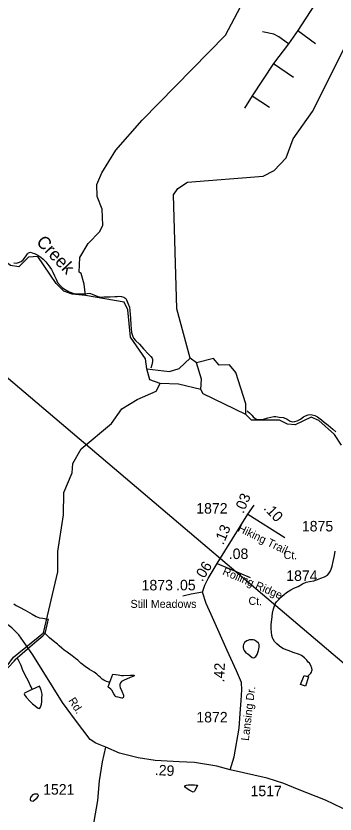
# Model space of a CAD drawing. Extents: x 2082433 to 2279600, y 546599 to 755198.
# Drawn here: x 2129173 to 2132963, y 651046 to 660530 of the extents above; entities that cross this region are included whole.
import ezdxf

# ---------------------------------------------------------------- set-up
doc = ezdxf.new("R2010")
doc.units = 0
for name, color, linetype in [('Exist Boundary Political Fire Districts', 7, 'Continuous'), ('Exist Hydrographic Creek Single Shore', 7, 'Continuous'), ('Exist Hydrographic Creek Single Shore Label', 7, 'Continuous'), ('Exist Hydrographic Misc Water Feature', 7, 'Continuous'), ('Exist Road Non-System Type 51', 7, 'Continuous'), ('Exist Road Secondary Mileage Hundredths English Label', 7, 'Continuous'), ('Exist Road Secondary Type 51 Attributed', 7, 'Continuous'), ('Exist Road Secondary Type 51 Label', 7, 'Continuous'), ('Exist Road Secondary Type 51 Number Label', 7, 'Continuous')]:
    doc.layers.add(name, color=color, linetype=linetype)

msp = doc.modelspace()

# ---------------------------------------------------------------- linework, layer by layer
at = {"layer": 'Exist Boundary Political Fire Districts'}
msp.add_lwpolyline([(2126117, 658742.4), (2137007.1, 649490.6)], dxfattribs=at)
at = {"layer": 'Exist Hydrographic Creek Single Shore'}
for points in [[(2129999.3, 657208.2), (2129982.3, 657342.9), (2129948.3, 657468.3), (2129923.3, 657485.2), (2129931.3, 657659), (2130030.3, 657827.5), (2130171.4, 657969), (2130204.4, 658043.8), (2130195.4, 658234.2), (2130136.3, 658386.3), (2130135.3, 658527.4), (2130193.4, 658667.3), (2130359.4, 658936.2), (2130674.4, 659293.8), (2131661.4, 660300.6), (2132454.5, 661803.2)], [(2129999.3, 657208.2), (2129841.2, 657224.5), (2129741.2, 657259.3), (2129649.3, 657349.8), (2129431.4, 657672.4), (2129323.3, 657664.8), (2129207.2, 657549), (2129107.4, 657564.2), (2128856.4, 657746.4)], [(2130728.3, 656337.1), (2130711.3, 656455.5), (2130535.3, 656711.7), (2130500.3, 657037.2), (2130458.2, 657129.9), (2129999.3, 657208.2)], [(2130887.2, 656163.3), (2130762.3, 656205.2), (2130728.3, 656337.1)], [(2129069.1, 652808.4), (2129144.2, 652908.5), (2129500.2, 653199.8), (2129672.2, 653924.5), (2129671.2, 654167.3), (2129736.2, 654602.2), (2129743.2, 654867.8), (2129842.2, 655102), (2129850.2, 655210.1), (2129949.3, 655385.2), (2130306.3, 655686.4), (2130430.1, 655861), (2130613.2, 655972), (2130837.2, 656072.5), (2130887.2, 656163.3)], [(2131371.3, 656091.1), (2131104.1, 656155.6), (2130887.2, 656163.3)], [(2131905.3, 655794.9), (2131396.3, 656041.4), (2131371.3, 656091.1)], [(2133040.2, 655430.7), (2132956.2, 655557), (2132772.2, 655721.5), (2132680.2, 655762.7), (2132489.3, 655671.5), (2132397.2, 655679.9), (2132305.3, 655727.7), (2131972.3, 655727.9), (2131905.3, 655794.9)]]:
    msp.add_lwpolyline(points, dxfattribs=at)
at = {"layer": 'Exist Hydrographic Misc Water Feature'}
msp.add_line((2131319.3, 656407.1), (2131244.2, 656464.4), dxfattribs=at)
for points in [[(2131244.2, 656464.4), (2131083.3, 657048.3), (2131044.3, 658403.9), (2131094.4, 658481.6), (2131210.4, 658554.7), (2132109.4, 658628.2), (2132242.4, 658694.4), (2132383.3, 658845.8), (2132466.4, 659070.4), (2132697.5, 659397), (2133267.3, 660530.3)], [(2129146.4, 657597.7), (2129180.7, 657593.7), (2129204.6, 657599.8), (2129234.2, 657614), (2129260.6, 657631.9), (2129276.4, 657650.2), (2129296.3, 657680.1), (2129312.1, 657704), (2129321.7, 657716.3), (2129334, 657720.2), (2129345.7, 657722.4), (2129365.6, 657716.6), (2129394.1, 657708.7), (2129434.1, 657688.8), (2129467.9, 657665), (2129498.1, 657641), (2129528.4, 657609.3), (2129576.4, 657545.6), (2129594.7, 657517.3), (2129612.9, 657485.8), (2129633, 657441.7), (2129649.4, 657401.5), (2129667.5, 657361.9), (2129697.6, 657326.1), (2129727.7, 657300), (2129759.7, 657278.2), (2129805.7, 657250.5), (2129859.6, 657232.6), (2129901.6, 657227.1), (2129943.9, 657227.2), (2129983.6, 657229.3)], [(2129983.6, 657229.3), (2130017.9, 657233.5), (2130042.1, 657235.4), (2130060.1, 657231.5), (2130080, 657225.7), (2130145.8, 657197.8), (2130186.2, 657190.1), (2130217.6, 657192.2), (2130294.1, 657194.5), (2130348, 657196.8), (2130376.1, 657197.1), (2130394, 657199.3), (2130427.6, 657195.4), (2130454, 657187.3), (2130478, 657171.5), (2130488.1, 657155.4), (2130504.1, 657117.7), (2130520.3, 657069.8), (2130526.6, 657031.5), (2130528.9, 656981.7), (2130533, 656939.7), (2130537.3, 656855.9), (2130541.8, 656815.9), (2130545.5, 656769.9), (2130555.7, 656731.9), (2130569.9, 656702.2), (2130594.3, 656672.1), (2130640.4, 656628.2), (2130688.6, 656574.7), (2130746.6, 656510.7), (2130775.1, 656484.9), (2130790.9, 656465.1), (2130795, 656451.1), (2130797.1, 656423.2), (2130789.1, 656385.1), (2130777.4, 656343.1)], [(2130728.3, 656337.1), (2130995.3, 656305.5), (2131111.3, 656339.2), (2131244.2, 656464.4)], [(2131905.3, 655794.9), (2131905.3, 655919.5), (2131786.2, 656292.6), (2131711.3, 656382.7), (2131586.2, 656382), (2131519.2, 656458.8), (2131319.3, 656407.1)], [(2131371.3, 656091.1), (2131378.3, 656215.7), (2131319.3, 656407.1)], [(2131919.1, 655836.1), (2131929.4, 655828.1), (2131947.6, 655812.3), (2131973.5, 655784.5), (2131991.5, 655764.7), (2132016.1, 655746.4), (2132040.1, 655734.7), (2132067.6, 655734.9), (2132113.7, 655738.9), (2132165.6, 655753.4), (2132199.6, 655761.6), (2132235.3, 655769.6), (2132259.5, 655769.6), (2132279.8, 655767.7), (2132299.5, 655763.9), (2132345.6, 655758.2), (2132377.6, 655748.1), (2132393.8, 655738.3), (2132429.9, 655714.6), (2132463.7, 655708.7), (2132485.7, 655710.6), (2132515.4, 655720.7), (2132551.5, 655738.8), (2132589.4, 655767.1), (2132611.6, 655777.2), (2132645.4, 655791.5), (2132671.3, 655793.3), (2132693.4, 655791.6), (2132725.2, 655783.9), (2132755.3, 655768), (2132801.7, 655730.2), (2132835.3, 655702.3), (2132883.7, 655668.6), (2132936.2, 655620.6), (2132972.1, 655586.7)], [(2132635, 652680.3), (2132646.7, 652692.3), (2132661, 652706.4), (2132677, 652720.6), (2132685, 652730.3), (2132688.3, 652748.4), (2132690.3, 652760.7), (2132686.4, 652780.4), (2132674.3, 652812.6), (2132658.3, 652838.6), (2132646, 652852.2), (2132628, 652876), (2132600.1, 652902.1), (2132563.8, 652929.9), (2132527.7, 652948), (2132477.7, 652963.7), (2132405.5, 652989.2), (2132351.8, 653011.1), (2132331.7, 653021), (2132303.4, 653042.7), (2132271.2, 653070.7), (2132245.6, 653098.5), (2132226.9, 653124.5), (2132218.9, 653140.3), (2132210.9, 653168.3), (2132207, 653206.2), (2132204.8, 653246.3), (2132206, 653300.4), (2132211.9, 653356.3), (2132221.6, 653434.3), (2132233.7, 653486.4), (2132253.2, 653542.3), (2132267.1, 653566.6), (2132299.1, 653600.6), (2132312.8, 653614.8), (2132358.6, 653656.9), (2132388.5, 653678.8), (2132438.7, 653708.9), (2132476, 653729.2), (2132524.4, 653751.5), (2132577.8, 653781.6), (2132620, 653802), (2132658.3, 653807.9), (2132709.8, 653818.4), (2132753.7, 653832.4), (2132795.9, 653850.8), (2132837.8, 653866.8), (2132873.9, 653886.8), (2132891.7, 653905.2), (2132905, 653929.1), (2132917.5, 653955.2), (2132929, 653991.2), (2132940.9, 654047.4), (2132958.3, 654119.4), (2132964.1, 654171.3)], [(2129146.2, 653544.8), (2129174.3, 653524.7), (2129216.5, 653504.9), (2129282.4, 653469.4), (2129366.6, 653421.8), (2129412.6, 653394.2), (2129434.7, 653383.9), (2129454.6, 653378.1), (2129492.7, 653372.3), (2129548.9, 653362.6), (2129558.8, 653360.7)], [(2129517.4, 653196.6), (2129523.3, 653206.6), (2129551, 653328.6), (2129558.8, 653360.7)], [(2129188.9, 652901.1), (2129197.1, 652909.2), (2129216.7, 652927.4), (2129308.6, 653009.6), (2129420, 653105.9), (2129491.7, 653164.4), (2129507.5, 653180.6), (2129517.4, 653196.6)], [(2130287.9, 652611.9), (2130278.1, 652613.8), (2130248, 652621.7), (2130218, 652635.9), (2130197.7, 652649.5), (2130171.7, 652671.3), (2130153.4, 652689.5), (2130133.7, 652709.1), (2130101.8, 652731.4), (2130045.4, 652763.1), (2129995.1, 652798.6), (2129945.3, 652840.6), (2129906.7, 652874.5), (2129880.5, 652896.2), (2129839.1, 652928.1), (2129782.5, 652967.9), (2129744.6, 652993.5), (2129716.3, 653017.2), (2129686.1, 653043.3), (2129666, 653063.4), (2129633.8, 653088.9), (2129571.9, 653140.9), (2129535.8, 653174.7), (2129517.4, 653196.6)], [(2131926.1, 652948.9), (2131977.8, 652907.5), (2131998.1, 652903.6), (2132012.2, 652909.6), (2132022.1, 652917.4), (2132039.9, 652943.5), (2132053.8, 652991.6), (2132063.3, 653027.6), (2132063.3, 653045.8), (2132061.8, 653061.9), (2132053, 653075.8), (2132031.3, 653097.7), (2132005.5, 653111.3), (2131991.3, 653115.5), (2131973.3, 653117.4), (2131949.1, 653115.4), (2131917.3, 653103.2), (2131889.2, 653085.1), (2131875.5, 653062.9), (2131871.4, 653046.9), (2131871.6, 653027), (2131875.9, 653006.9), (2131885.7, 652989.1), (2131905.8, 652962.9), (2131926.1, 652948.9)], [(2129053.9, 652756.5), (2129085.5, 652792.7), (2129151.3, 652861), (2129177.2, 652889.1), (2129188.9, 652901.1)], [(2129366.6, 652525.9), (2129360.7, 652536.1), (2129352.5, 652556), (2129342, 652577.8), (2129326.2, 652615.9), (2129304.3, 652661.8), (2129279.7, 652703.6), (2129251.4, 652763.5), (2129233.6, 652811.2), (2129202.8, 652875.1), (2129188.9, 652901.1)], [(2130287.9, 652611.9), (2130325.5, 652710.1), (2130385.7, 652698.6), (2130425.5, 652692.5), (2130449.5, 652690.9), (2130535.4, 652697), (2130571.7, 652697.2), (2130577.5, 652693.5), (2130577.7, 652687.3), (2130573.4, 652685.1), (2130531.3, 652667.2), (2130449.9, 652634.9), (2130428, 652622.8), (2130414.3, 652606.7), (2130406.3, 652584.7), (2130406.3, 652566.5), (2130412.2, 652548.6), (2130430.5, 652504.8), (2130450.8, 652458.8), (2130450.3, 652446.7), (2130448.9, 652434.7), (2130444.8, 652428.8), (2130438.9, 652422.8), (2130432.9, 652422.9), (2130416.9, 652426.6), (2130386.6, 652436.4), (2130364.8, 652440.5), (2130356.4, 652444.2), (2130350.7, 652452.4), (2130336.3, 652476.4), (2130312.3, 652518.2), (2130300.2, 652530.2), (2130280.6, 652544.1), (2130272.2, 652548.2), (2130270.5, 652557.8), (2130272.2, 652568.1), (2130275.8, 652578.1), (2130287.9, 652611.9)], [(2132635, 652680.3), (2132649.1, 652676.5), (2132613.4, 652564.3), (2132555.2, 652584), (2132594.8, 652694.1), (2132635, 652680.3)], [(2129366.6, 652525.9), (2129336.5, 652513.8), (2129274.6, 652481.8), (2129272.7, 652475.6), (2129274.6, 652463.5), (2129293, 652433.6), (2129337.3, 652388), (2129369.3, 652355.9), (2129435.5, 652304.5), (2129449.5, 652298.4), (2129457.3, 652302.5), (2129463.6, 652314.5), (2129475.3, 652352.4), (2129479.2, 652380.6), (2129481.3, 652420.5), (2129482.7, 652472.6), (2129474.7, 652516.4), (2129466.5, 652538.3), (2129454.2, 652564.5), (2129366.6, 652525.9)], [(2131315, 651355), (2131295.4, 651318.7), (2131287.2, 651310.9), (2131279.4, 651306.9), (2131271.2, 651308.9), (2131239.4, 651324.7), (2131205.1, 651346.5), (2131186.9, 651362.2), (2131180.9, 651374.5), (2131180.9, 651380.1), (2131188.7, 651386.3), (2131201, 651390.5), (2131217, 651392.5), (2131265, 651394.6), (2131295, 651393), (2131312.8, 651391), (2131330.8, 651389.1), (2131315, 651355)], [(2129412.4, 651228.8), (2129382.6, 651198.4), (2129374.6, 651196.4), (2129360.5, 651198.5), (2129350.4, 651204.5), (2129346.1, 651212.5), (2129344.3, 651226.5), (2129348.2, 651242.1), (2129356.2, 651256.4), (2129378.1, 651278.6), (2129393.9, 651284.7), (2129416.1, 651286.6), (2129425.9, 651284.7), (2129433.9, 651276.6), (2129435.7, 651270.7), (2129437.8, 651264.7), (2129435.9, 651258.9), (2129430, 651248.9), (2129412.4, 651228.8)]]:
    msp.add_lwpolyline(points, dxfattribs=at)
at = {"layer": 'Exist Road Non-System Type 51'}
for points in [[(2132772.8, 660747.7), (2132521.6, 660357.2)], [(2132410.7, 660201), (2132295.3, 660282.7), (2132236.7, 660312.8), (2132100, 660343)], [(2132521.6, 660357.2), (2132410.7, 660201)], [(2132521.6, 660357.2), (2132731.1, 660202.8)], [(2132410.7, 660201), (2132232.3, 659964.9)], [(2132232.3, 659964.9), (2131977.6, 659581.5)], [(2132232.3, 659964.9), (2132468.4, 659801.6)], [(2131977.6, 659581.5), (2131887, 659434.2)], [(2131977.6, 659581.5), (2132183.5, 659448.4)]]:
    msp.add_lwpolyline(points, dxfattribs=at)
at = {"layer": 'Exist Road Secondary Type 51 Attributed'}
for p, q in [((2131927.4, 654608.5), (2132002.4, 654717.2)), ((2131563.4, 654025), (2131927.4, 654608.5)), ((2131927.4, 654608.5), (2132368.1, 654330.8)), ((2131563.4, 654025), (2131955.9, 653857.7))]:
    msp.add_line(p, q, dxfattribs=at)
for points in [[(2131390.1, 653684.3), (2131416.8, 653766.3), (2131454.7, 653844.7), (2131563.4, 654025)], [(2131390.1, 653684.3), (2131254.7, 653659.3), (2131156.3, 653633.4)], [(2131719.5, 651573.4), (2131766.1, 651726.9), (2131823, 652067.6), (2131835.1, 652240.9), (2131847.2, 652397.1), (2131857.5, 652521.2), (2131852.4, 652607.5), (2131792, 652746.4), (2131681.6, 652991.3), (2131491.8, 653418.2), (2131432.3, 653548.1), (2131390.1, 653684.3)], [(2130239.5, 651839), (2130123.9, 651887.3), (2130056.6, 651933.9), (2129880.7, 652159.9), (2129724.5, 652371.1), (2129373.6, 652936.4), (2129207.3, 653176.8), (2129124.5, 653258.1), (2129045, 653317), (2128935.2, 653363.2), (2128709.2, 653438), (2128579, 653480.5)], [(2129659.9, 649602.6), (2129830.7, 649866.5), (2129877.2, 649963.1), (2129932.4, 650147.7), (2130048, 650639.3), (2130146.3, 651208.5), (2130166.9, 651440.3), (2130200.4, 651664.9), (2130239.5, 651839)], [(2131719.5, 651573.4), (2131559.1, 651616.5), (2131295.9, 651660.1), (2131113.7, 651668), (2130825.7, 651684), (2130626.8, 651715.8), (2130404, 651771.5), (2130239.5, 651839)], [(2134923.2, 649835.7), (2134846, 649879.3), (2134753.3, 649943.9), (2134535.3, 650146.3), (2134379.3, 650273.1), (2134195.6, 650428.4), (2134062.9, 650517.3), (2133504.5, 650872.4), (2133147.2, 651070), (2132848.3, 651209.2), (2132518.8, 651343.3), (2132356.1, 651409.5), (2132157.2, 651472.4), (2131719.5, 651573.4)]]:
    msp.add_lwpolyline(points, dxfattribs=at)

# ---------------------------------------------------------------- texts
at = {"layer": 'Exist Hydrographic Creek Single Shore Label'}
msp.add_text('Creek', height=150, rotation=313.56378, dxfattribs=at).set_placement((2129405.8, 657836.4))
at = {"layer": 'Exist Road Secondary Mileage Hundredths English Label'}
for s, rotation, p in [('.03', 66.95978, (2131874.7, 654610)), ('.10', 313.31397, (2132107.1, 654675.1)), ('.13', 66.95991, (2131636.1, 654237.8)), ('.08', 0.15892, (2131701.2, 654076.2)), ('.06', 58.10587, (2131385.8, 653800.5)), ('.05', 0.20057, (2131075.8, 653704.1)), ('.42', 88.02599, (2131647.8, 652609.5)), ('.29', 356.83555, (2130819.8, 651509.8))]:
    msp.add_text(s, height=125, rotation=rotation, dxfattribs=at).set_placement(p)
at = {"layer": 'Exist Road Secondary Type 51 Label'}
for s, rotation, p in [('Hiking Trail', 334.04123, (2131799.9, 654410.5)), ('Ct.', 357.6229, (2132350.7, 654079.1)), ('Rolling Ridge', 336.64444, (2131619.2, 653896.6)), ('Ct.', 357.6229, (2131933.7, 653534)), ('Lansing Dr.', 83.06839, (2131938.7, 651912.7)), ('Rd.', 302.77399, (2129792, 652394.4))]:
    msp.add_text(s, height=95, rotation=rotation, dxfattribs=at).set_placement(p)
msp.add_text('Still Meadows', height=95, dxfattribs=at).set_placement((2130534.7, 653496.2))
at = {"layer": 'Exist Road Secondary Type 51 Number Label'}
for s, p in [('1872', (2131314.8, 654616.3)), ('1875', (2132569.5, 654404.5)), ('1874', (2132383.8, 653816.2)), ('1873', (2130665.8, 653703.7)), ('1872', (2131316.1, 652134.9)), ('1521', (2129495.7, 651276.6)), ('1517', (2131959.7, 651258))]:
    msp.add_text(s, height=125, dxfattribs=at).set_placement(p)

doc.saveas('drawing.dxf')
